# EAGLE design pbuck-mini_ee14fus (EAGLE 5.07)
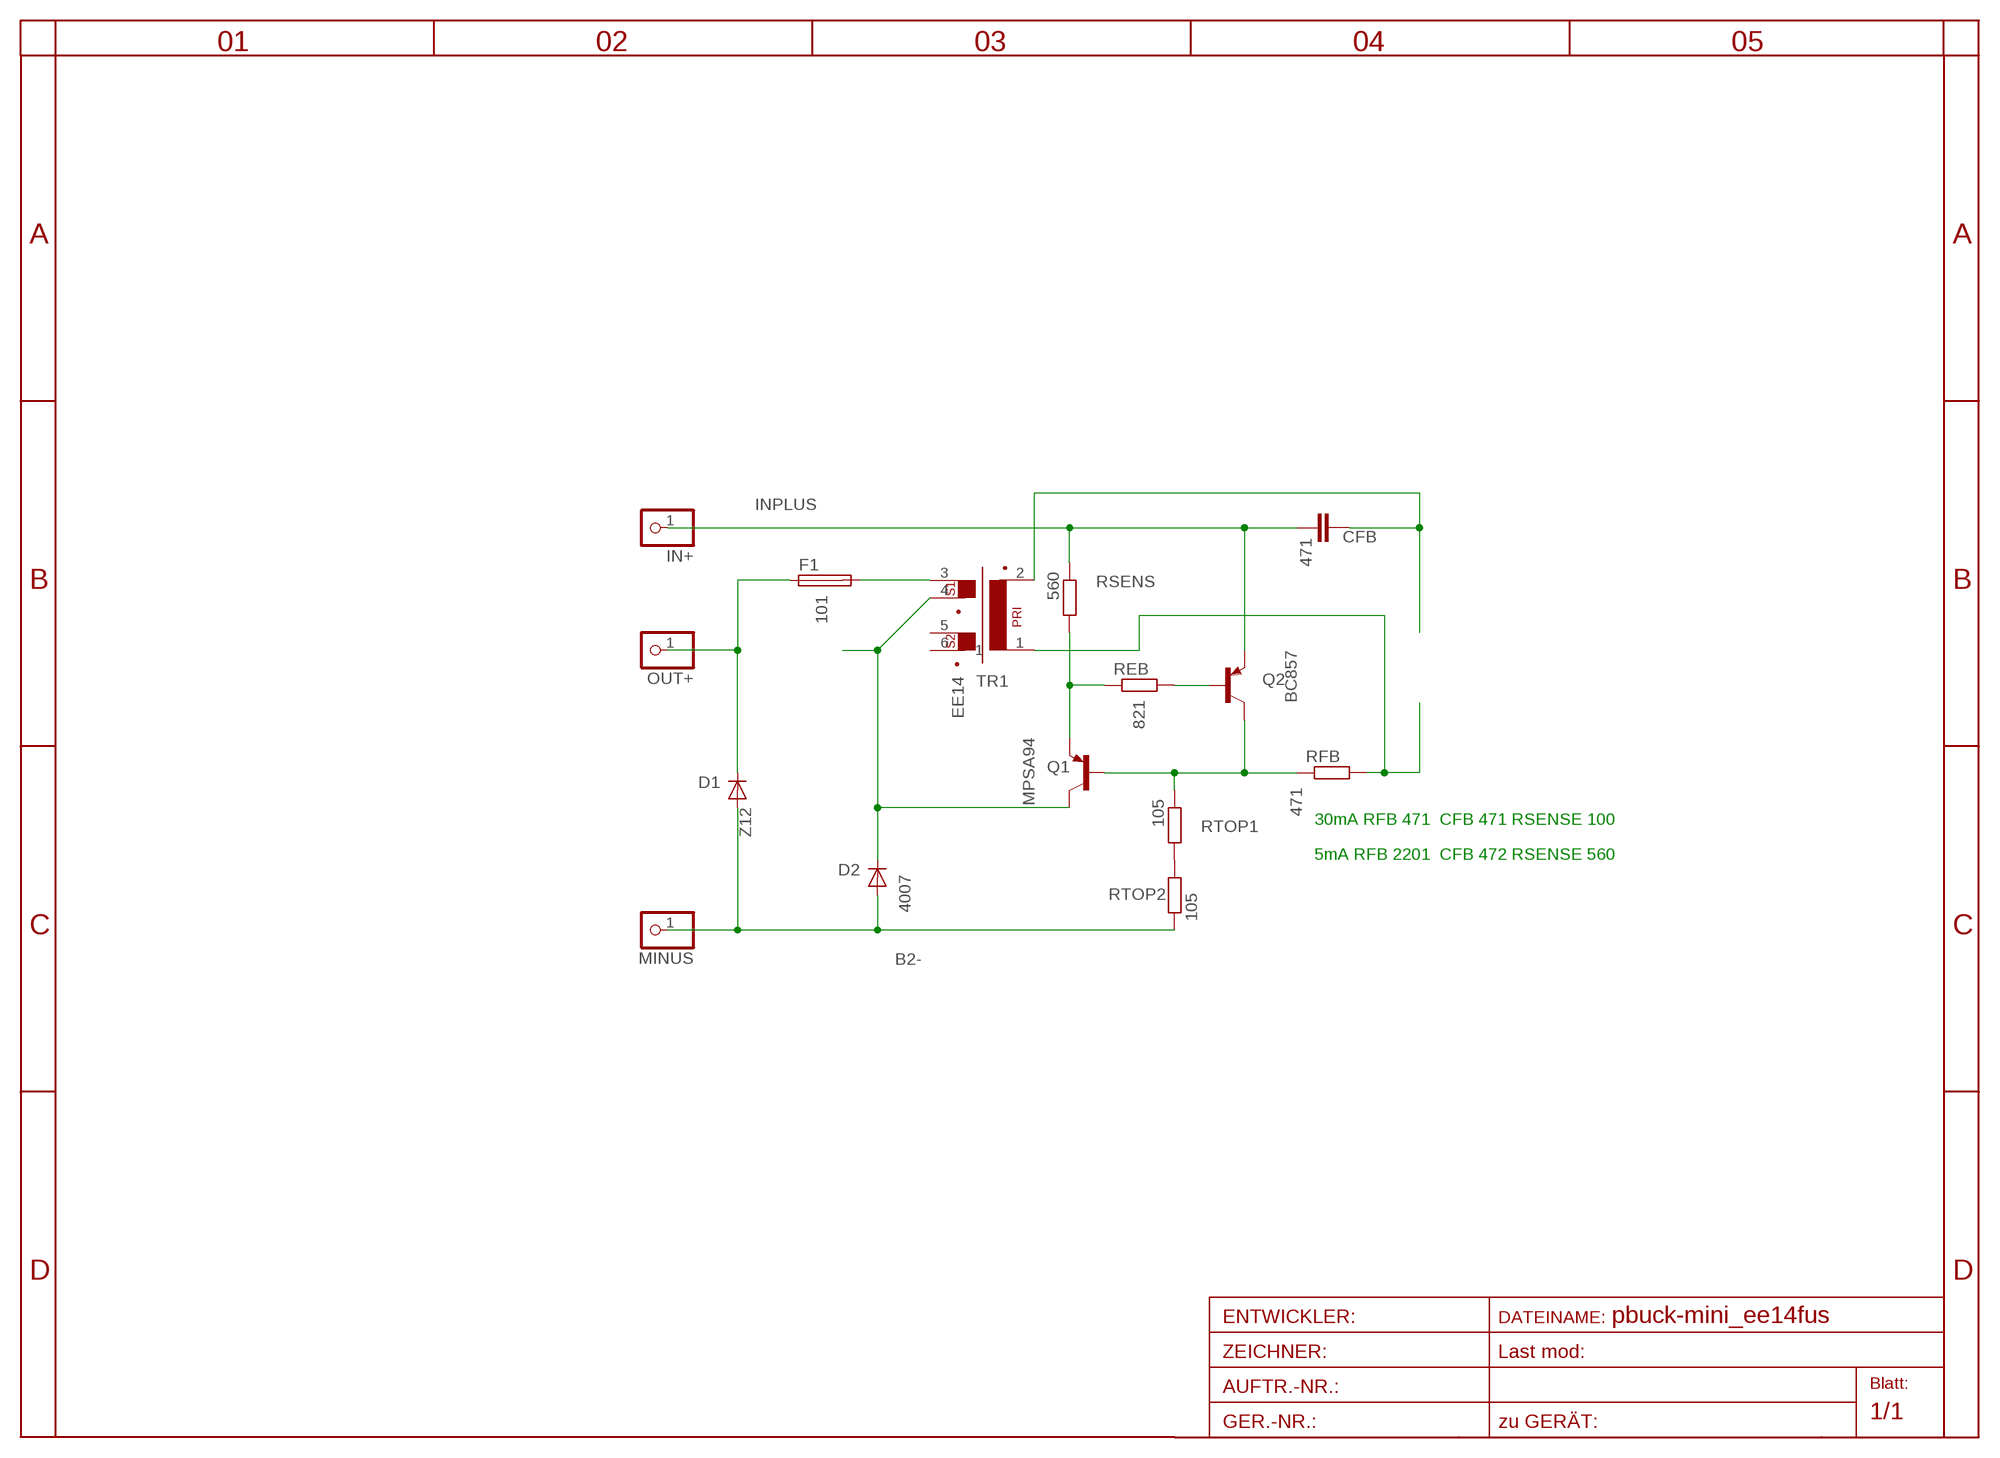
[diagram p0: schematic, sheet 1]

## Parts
CFB  471  C-EUC0805  [C0805]
D1  Z12  DIODE-MINIMELF  [MINIMELF]
D2  4007  DIODE-SMA-DO214  [SMA-DO214AC]
F1  101  195592  [19559-2]
IN+  PINHD-1X11MM0  [1X1MM0]
MINUS  PINHD-1X11MM0  [1X1MM0]
OUT+  PINHD-1X11MM0  [1X1MM0]
Q1  MPSA94  MPSW92  [TO92-CBE]
Q2  BC857  BC857ALT1SMD  [SOT23-BEC]
REB  821  R-EU_R1206  [R1206]
RFB  471  R-EU_R0805  [R0805]
RSENS  560  R-EU_R1206  [R1206]
RTOP1  105  R-EU_R1206  [R1206]
RTOP2  105  R-EU_R1206  [R1206]
TR1  EE14  EE14EE14  [EE14]

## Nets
B2-: D1.A D2.A MINUS.1 RTOP2.1
B92: Q1.B Q2.C RFB.1 RTOP1.1
B_OUT: D1.C F1.1 OUT+.1
C92: D2.K(C) Q1.C TR1.4
EB: Q1.E REB.1 RSENS.2
INPLUS: CFB.2 IN+.1 Q2.E RSENS.1
L4DOT: CFB.1 TR1.2
L4NO: RFB.2 TR1.1
N$1: F1.2 TR1.3
N$11: RTOP1.2 RTOP2.2
N$12: Q2.B REB.2
Unconnected: TR1.5 TR1.6

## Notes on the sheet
- 30mA RFB 471  CFB 471 RSENSE 100
- 5mA RFB 2201  CFB 472 RSENSE 560

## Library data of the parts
CFB = rcl:C-EU: CAPACITOR, European symbol
D1 D2 = diode:DIODE-: DIODE
F1 = fuse:19559: FUSE HOLDER
IN+ MINUS OUT+ = pinhead:PINHD-1X1: PIN HEADER
Q1 = transistor-pnp:MPSW92*: PNP Transistror
Q2 = transistor-pnp:BC857*: PNP Transistror
REB RFB RSENS RTOP1 RTOP2 = rcl:R-EU_: RESISTOR, European symbol
TR1 = trafo:EE14

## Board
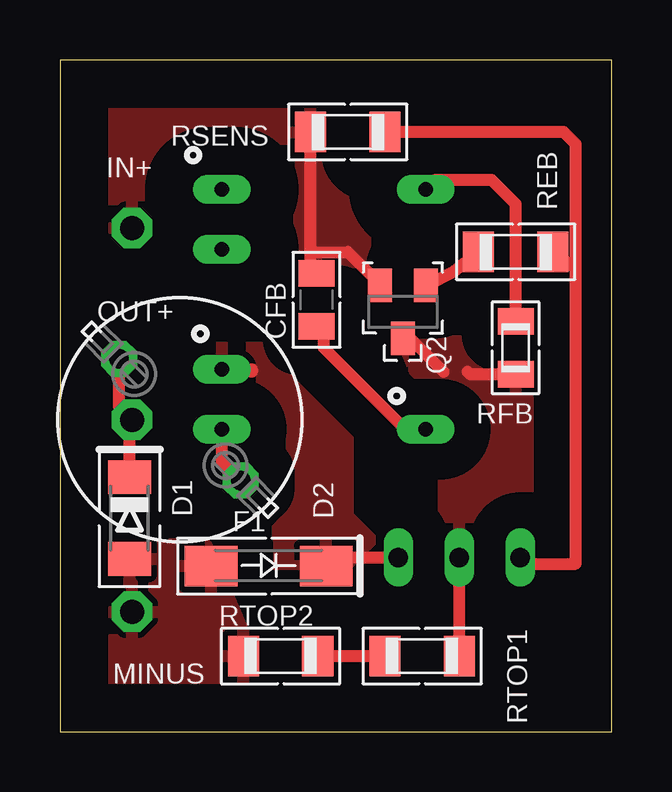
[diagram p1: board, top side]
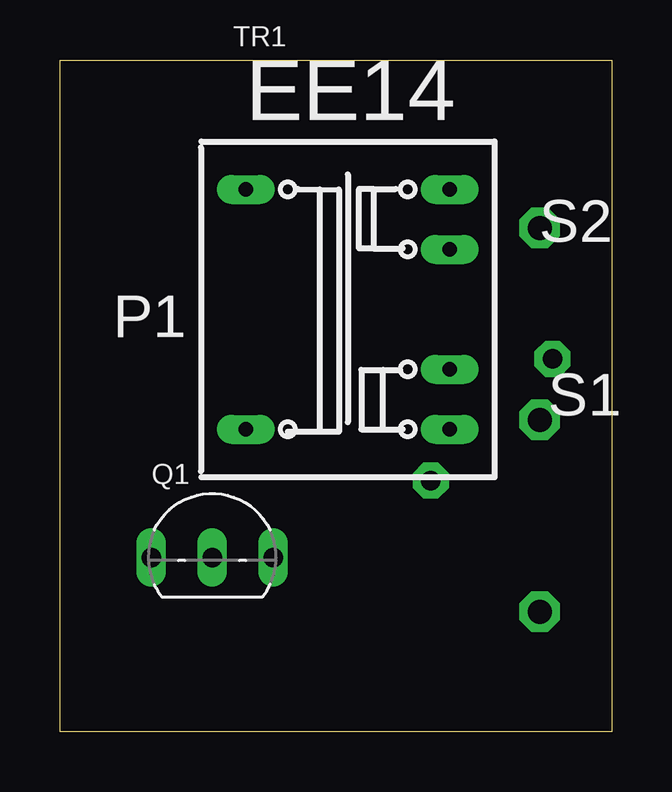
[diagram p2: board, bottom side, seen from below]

Size 23 x 28 mm. Coordinates in mm from the lower left corner, seen from the top.
Outline: 0,0 23,0 23,28 0,28 0,0
Copper layers (1*16): Top 0.035mm / dielectric 1.5mm / Bottom 0.035mm
Design rules "default *": minimum track width 10mil, minimum drill 20mil, track to track 8mil, track to pad 8mil, pad to pad 8mil, via to via 8mil, smd to smd 8mil, copper to edge 2mm, drill to drill 8mil, minimum pad ring 8mil, minimum via ring 8mil, stop-mask expansion 4mil, vias tented up to drill 0mil, thermal gap 10mil

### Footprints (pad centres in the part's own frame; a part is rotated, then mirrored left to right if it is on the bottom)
C0805 = smd 1.1 x 1.5: 1 -1.1,0; 2 1.1,0
MINIMELF = smd 1.4 x 1.8: A 1.7,0; C -1.7,0
SMA-DO214AC = smd 2.2 x 1.7: A 2.4,0; K -2.4,0
19559-2 = drill 0.8 pad 1.5 octagon: 1 -2.54,2.54; 2 2.54,-2.54
1X1MM0 = drill 1 pad 1.676 octagon: 1 0,0
TO92-CBE = drill 0.813 long: B 0,0; C 2.54,0; E -2.54,0
SOT23-BEC = smd 1 x 1.4: B -0.95,-1.1; C 0,1.1; E 0.95,-1.1
R1206 = smd 1.3 x 1.7: 1 -1.55,0; 2 1.55,0
R0805 = smd 1.1 x 1.5: 1 -1.1,0; 2 1.1,0
EE14 = drill 0.6 pad 1.2 long: 1 4.25,-5; 2 4.25,5; 3 -4.25,5; 4 -4.25,2.5; 5 -4.25,-2.5; 6 -4.25,-5

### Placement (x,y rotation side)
CFB  10.7,18 90 top
D1  2.9,8.9 270 top
D2  8.7,6.9 180 top
F1  5,13 0 top
IN+  3,21 0 top
MINUS  3,5 0 top
OUT+  3,13 0 top
Q1  16.65,7.26 0 bottom
Q2  14.3,17.5 180 top
REB  19,20 180 top
RFB  19,16 90 top
RSENS  12,25 0 top
RTOP1  15.1,3.15 180 top
RTOP2  9.2,3.15 0 top
TR1  11,17.6 180 bottom

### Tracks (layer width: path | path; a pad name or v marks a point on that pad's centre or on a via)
B2-
  pour Top (isolate 2, rank 2): 2,8 6,8 9,1 2,1
B92
  Top 0.5: RTOP1.1 Q1.B | Q2.C 14.6,16.4 16,15 | RFB.1 17.1,14.9 17,15
  pour Top (isolate 1.5, rank 3): 14,17 21,17 20,10 16,7 16,12
B_OUT
  Top 0.5: F1.1 2.46,13.54 OUT+.1 2.9,12.9 D1.C
C92
  Top 0.5: Q1.C 11,7.26 11,7 11.1,7 D2.K | TR1.4 8,15.1 8,15
  pour Top (isolate 1.5, rank 2): 6,16 6,14 8,12 8,7 12,7 13,8 12,9 12,13 9,16
EB
  Top 0.5: Q1.E 19.19,7 21.5,7 21.5,19.3 | 21.5,19.3 REB.1 | RSENS.2 21,25 21.5,24.5 21.5,19.3
INPLUS
  Top 0.5: 10.45,20 10.45,19.35 CFB.2 | 10.45,20 RSENS.1 | Q2.E 13.35,18.65 12,20 10.45,20
  pour Top (isolate 2): 2,26 14,26 14,18 10,18 10,21 2,21
L4DOT
  Top 0.5: TR1.2 14.4,12.6 11,16 11,16.6 CFB.1
L4NO
  Top 0.406: TR1.1 14.25,22.58
  Top 0.5: RFB.2 19,22 18,23 15.65,23 TR1.1
N$1
  Top 0.406: TR1.3 5.75,12.63
  Top 0.5: TR1.3 6.75,11.25 F1.2
N$11
  Top 0.5: RTOP2.2 RTOP1.2
N$12
  Top 0.5: REB.2 16.45,19.2 Q2.B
